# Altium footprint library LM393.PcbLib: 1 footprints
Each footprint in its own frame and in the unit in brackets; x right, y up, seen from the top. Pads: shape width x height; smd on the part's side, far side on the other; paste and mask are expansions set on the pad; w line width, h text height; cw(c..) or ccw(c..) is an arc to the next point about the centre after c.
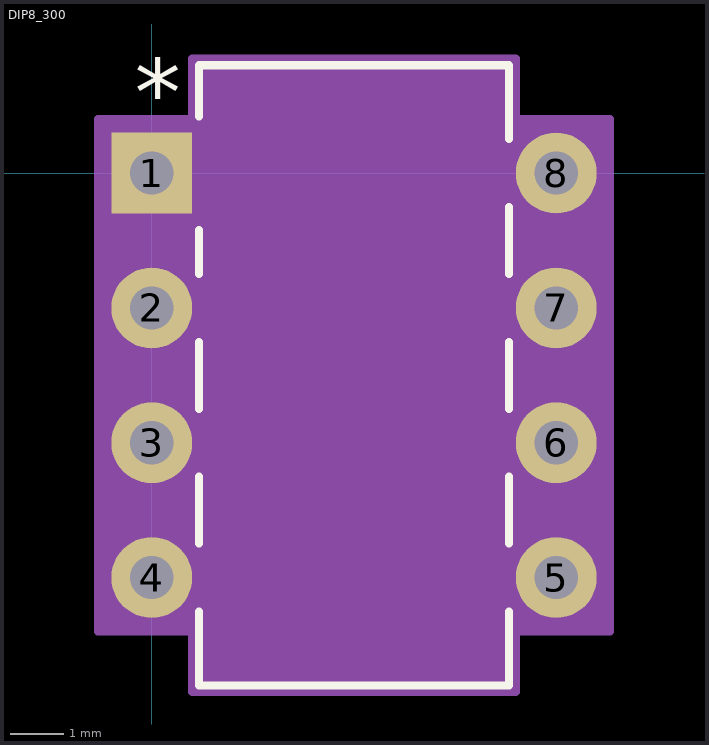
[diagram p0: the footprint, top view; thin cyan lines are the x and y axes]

## DIP8_300 [mil]
pads (8):
  rect 60x60 hole 32 paste-30 mask+0: 1(0,0)
  round 60 hole 32 paste-30 mask+0: 2(0,-100) 3(0,-200) 4(0,-300) 5(300,-300) 6(300,-200) 7(300,-100) 8(300,0)
Top Overlay:
  lines w6: 35,-325.15 35,-380 265,-380 265,-325.15 ; 35,-274.85 35,-225.15 ; 35,-174.85 35,-125.15 ; 35,-74.85 35,-42.11 ; 35,42.11 35,80 265,80 265,25.15 ; 265,-274.85 265,-225.15 ; 265,-174.85 265,-125.15 ; 265,-74.85 265,-25.15
  text "*" at -12.5,35 h50
  text ".Designator" at 12.5,-175 h50
Mechanical 13:
  lines w1: 138,75 ccw(c150,75) 162,75 ; -16,-316 -16,-284 40,-284 40,-316 -16,-316 ; -16,-216 -16,-184 40,-184 40,-216 -16,-216 ; -16,-116 -16,-84 40,-84 40,-116 -16,-116 ; -16,-16 -16,16 40,16 40,-16 -16,-16 ; 40,-375 260,-375 260,75 40,75 40,-375 ; 260,-316 260,-284 316,-284 316,-316 260,-316 ; 260,-216 260,-184 316,-184 316,-216 260,-216 ; 260,-116 260,-84 316,-84 316,-116 260,-116 ; 260,-16 260,16 316,16 316,-16 260,-16
  text ".Designator" at 12.5,-175 h50
  text "*" at 37.5,-25 h50
Mechanical 15:
  region: 270,-340 340,-340 340,40 270,40 270,85 30,85 30,40 -40,40 -40,-340 30,-340 30,-385 270,-385
  lines w6: -40,-340 -40,40 30,40 30,85 270,85 270,40 340,40 340,-340 270,-340 270,-385 30,-385 30,-340 -40,-340
3D body "DIP8_300.step": height 205.12, standoff -100, extent -5,-375 315,75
